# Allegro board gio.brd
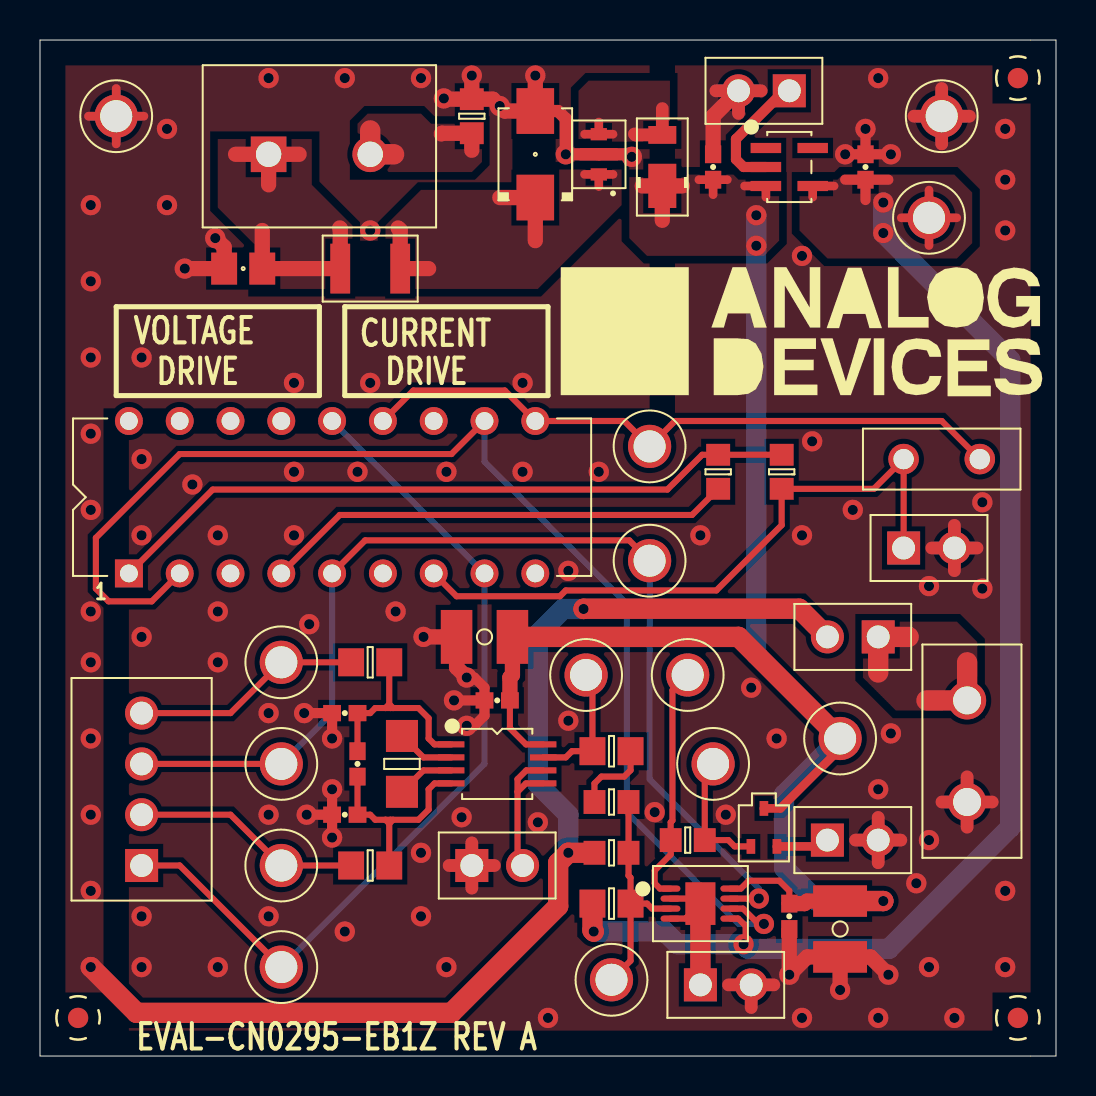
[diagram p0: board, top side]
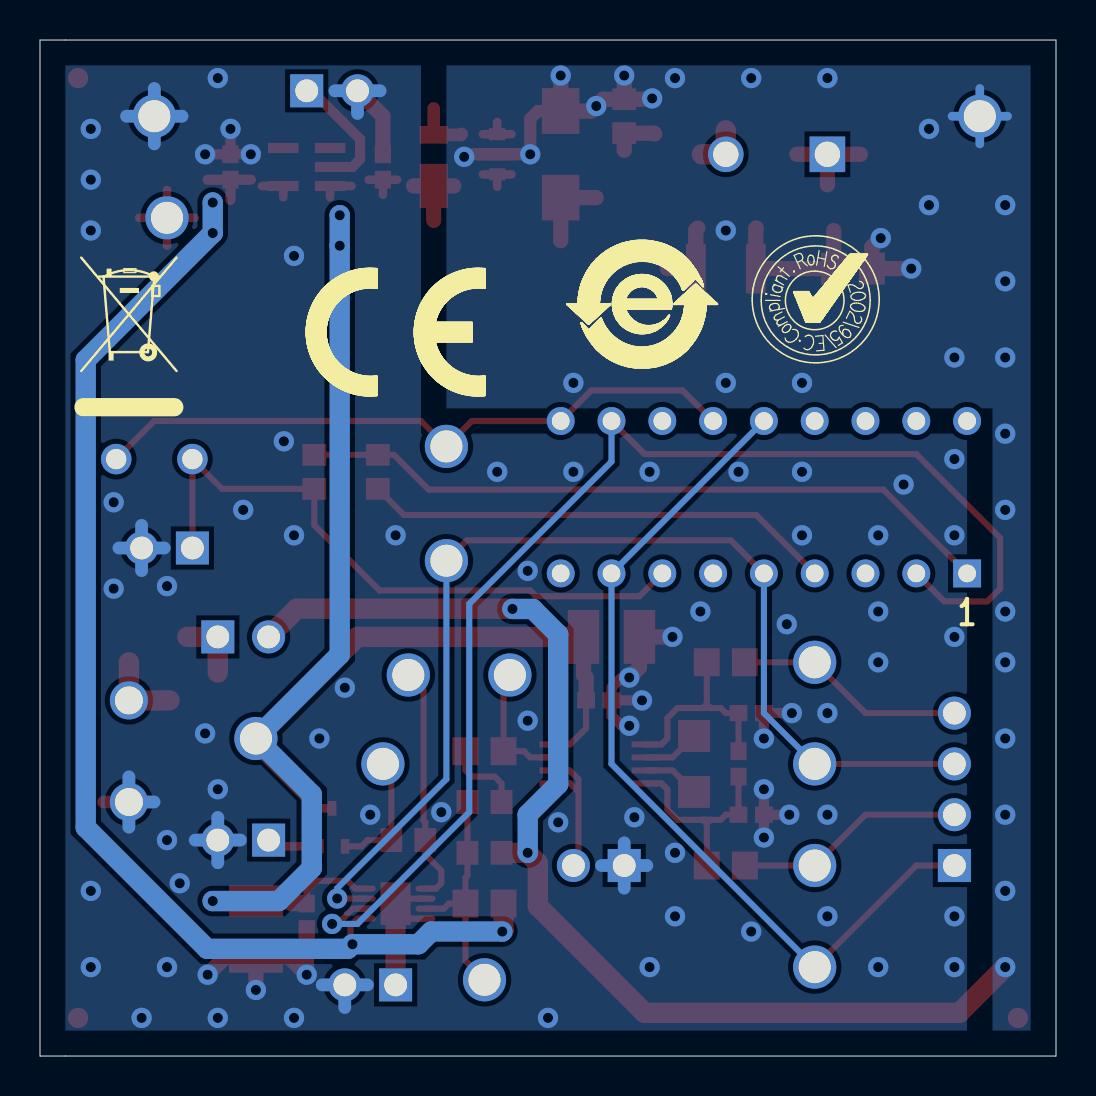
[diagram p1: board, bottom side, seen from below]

Outline 50.8 x 50.8 mm; copper layers: TOP, BOTTOM. Coordinates in mm from the lower left corner of the outline.
Outline path: 0,50.8 50.8,50.8 50.8,0 0,0 0,50.8

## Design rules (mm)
nets with their own width: min track width 0.508; nets AGND

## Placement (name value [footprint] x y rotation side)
C1  1000pF  [C0402]  15.24 17.14 180 top
C2  1000pF  [C0402]  15.24 12.06 0 top
C3  10000pF  [C0402]  15.88 14.6 270 top
C4  10uF  [C1210]  22.23 20.96 0 top
C5  1000pF  [C0402]  22.86 17.78 0 top
C6  10uF  [C1210]  40.01 6.35 90 top
C7  1000pF  [C0402]  37.47 6.99 90 top
C8  1000pF  [C0402]  33.66 44.45 270 top
C9  1000pF  [C0402]  41.27 44.45 270 top
C10  4.7UF  [C0805]  10.16 39.37 0 top
D1  SMAZ36-TP  [DIOSMJ5_0]  24.77 45.09 90 top
D2  SBR2U30P1-7  [POWERDI123]  31.12 44.45 90 top
F1  0.20A  [F1210]  16.51 39.37 0 top
FL1  0.1uF  [FSM0805L79W49H34]  27.94 45.09 90 top
GND  K24A W. EYELET T15.23  [CNLOOPTP]  45.09 46.99 0 top
GNDSNS  K24A W. EYELET T15.23  [CNLOOPTP]  12.06 4.45 0 top
J1  M20-9990246  [CNHARWIN-M20-9990246]  21.59 9.53 0 top
J2  OSTTC022162  [CN1X2H406]  11.43 45.09 0 top
J3  282834-4  [CN1X4H406]  5.08 9.53 90 top
J4  M20-9990246  [CNHARWIN-M20-9990246]  33.02 3.56 0 top
J5  M20-9990246  [CNHARWIN-M20-9990246]  37.47 48.26 180 top
J6  M20-9990246  [CNHARWIN-M20-9990246]  41.91 20.96 180 top
J7  M20-9990246  [CNHARWIN-M20-9990246]  43.18 25.4 0 top
J8  M20-9990246  [CNHARWIN-M20-9990246]  39.37 10.79 0 top
LOOPGND  K24A W. EYELET T15.23  [CNLOOPTP]  3.81 46.99 0 top
NOREF  -  []  0 0 0 top
NOREF#2  -  []  -132.72 -239.08 0 top
NOREF#3  -  [unnamed#2]  1.91 1.91 0 top
NOREF#4  -  []  76.2 0 90 top
NOREF#5  -  [unnamed#2]  48.9 48.9 0 top
NOREF#6  -  []  0 50.8 0 top
NOREF#7  -  []  -30.8 140.02 0 top
NOREF#8  -  []  1.91 1.91 0 top
NOREF#9  -  []  50.8 50.8 180 top
NOREF#10  -  []  38.73 36.2 0 top
NOREF#11  -  []  0 0 0 top
NOREF#12  -  []  24.64 73.91 0 top
NOREF#13  -  []  -132.72 -239.08 0 top
NOREF#14  -  []  -132.72 -239.08 0 top
NOREF#15  -  []  0 50.8 270 top
NOREF#16  -  []  0 0 0 top
NOREF#17  -  []  50.8 0 90 top
NOREF#18  -  []  0 50.8 0 top
NOREF#19  -  [unnamed#2]  48.9 1.91 0 top
NOREF#20  -  []  -15.88 -47.12 0 top
NOREF#21  -  []  1.91 1.91 0 top
NOREF#22  -  []  50.8 0 0 top
NOREF#23  -  []  31.5 36.2 180 bottom
NOREF#24  -  []  12.06 37.72 180 bottom
NOREF#25  -  []  46.36 37.08 180 bottom
NOREF#26  -  []  20.7 37.59 180 bottom
Q1  2SD2703TL  [TUMT3]  36.2 11.43 0 top
R1  4.02K  [R0805]  16.51 19.69 0 top
R2  4.02K  [R0805]  16.51 9.53 0 top
R3  1K  [R1206]  18.1 14.6 90 top
R4  2.5K  [RCK02]  43.18 29.85 0 top
R5  10K  [R0603]  33.91 29.21 90 top
R6  10K  [R0603]  37.08 29.21 90 top
R7  249  [R0603]  21.59 46.99 90 top
R8  2.0K  [R0805]  28.58 15.24 0 top
R9  30K  [R0603]  28.58 12.7 0 top
R10  1K  [R0603]  28.58 10.16 0 top
R11  30K  [R0603]  32.38 10.79 0 top
R12  130K  [R0805]  28.58 7.62 180 top
R13  10  [TO220AC-RA]  46.36 17.78 270 top
S1  ASE6204  [SWDIP18]  4.45 24.13 0 top
SUPPLYSNS  K24A W. EYELET T15.23  [CNLOOPTP]  12.06 14.6 0 top
TP1  K24A W. EYELET T15.23  [CNLOOPTP]  32.38 19.05 0 top
TP2  K24A W. EYELET T15.23  [CNLOOPTP]  44.45 41.91 0 top
TP3  K24A W. EYELET T15.23  [CNLOOPTP]  33.66 14.6 0 top
TP4  K24A W. EYELET T15.23  [CNLOOPTP]  27.3 19.05 0 top
TP5  K24A W. EYELET T15.23  [CNLOOPTP]  28.58 3.81 0 top
TP6  K24A W. EYELET T15.23  [CNLOOPTP]  30.48 24.77 0 top
TP7  K24A W. EYELET T15.23  [CNLOOPTP]  30.48 30.48 0 top
TP8  K24A W. EYELET T15.23  [CNLOOPTP]  40.01 15.88 0 top
U1  AD8226BRMZ  [MSOP8]  22.86 14.6 270 top
U2  ADA4091-2ACPZ  [QFN8_3X3_PAD2_13X1_5]  33.02 7.62 270 top
U3  ADR02BUJZ  [TSOT-5]  37.47 44.45 270 top
UNK+V  K24A W. EYELET T15.23  [CNLOOPTP]  12.06 9.53 0 top
UNK-V  K24A W. EYELET T15.23  [CNLOOPTP]  12.06 19.69 0 top

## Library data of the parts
C1 C2 C5 C7-C9 = CAP: Tolerance: 5; User Part Number: UPN; alternate symbols: (C0402H22_ALT,C0201-2); part number: CAP_SM-1000PF,50V,5,E012419,C0402; tolerance: 5
C3 = CAP: Tolerance: 10; User Part Number: UPN; alternate symbols: (C0402H22_ALT,C0201-2); part number: CAP_SM-10000PF,25V,10,E013688,C0402; tolerance: 10
C4 C6 = CAP: Tolerance: 10; User Part Number: UPN; alternate symbols: (C0402H22_ALT,C0201-2); part number: CAP_SM-10UF,25V,10,E011786,C1210; tolerance: 10
C10 = CAP: Tolerance: 10; User Part Number: UPN; alternate symbols: (C0402H22_ALT,C0201-2); part number: CAP_SM-4.7UF,25V,10,E006908,C0805; tolerance: 10
D1 = DIOZNR: Tolerance: 5; User Part Number: UPN; part number: DIOZNR_SM-SMAZ36-TP,36V,5,E017811,DIOSMJ5_0; tolerance: 5
D2 = DIO: User Part Number: UPN; Tolerance: N/A; part number: DIO_SM-SBR2U30P1-7,30V,N/A,E016912,POWERDI123; tolerance: N/A
F1 = FSFUSE: User Part Number: UPN; part number: FSFUSE_SM-0.20A,30V,E016947,F1210
FL1 = FLTR3P: Tolerance: 20; User Part Number: UPN; part number: FLTR3P_SM-0.1UF,E010964,FSM0805L79W49H34; tolerance: 20
GND GNDSNS LOOPGND SUPPLYSNS TP1-TP8 UNK+V UNK-V = CNTP1P: User Part Number: UPN; part number: CNTP1P_TH-K24A W. EYELET T15.23,E005673,CNLOOPTP
J1 J4-J8 = CN2P: User Part Number: UPN; part number: CN2P_TH-M20-9990246,E010843,CNHARWIN-M20-9990246
J2 = CN2P: User Part Number: UPN; part number: CN2P_TH-OSTTC022162,E016936,CN1X2H406
J3 = CN4P: User Part Number: UPN; part number: CN4P_TH-282834-4,E016935,CN1X4H406
Q1 = TRAN2N3904SOT23: User Part Number: UPN; part number: TRAN2N3904SOT23_SM-2SD2703TL,E016915,TUMT3
R1 R2 = RES: Tolerance: 1; User Part Number: UPN; alternate symbols: (RRAD984L1500W75H520LD32); part number: RES_SM-4.02K,1/8W,1,E003522,R0805; tolerance: 1
R3 = RES: Tolerance: 0.05; User Part Number: UPN; alternate symbols: (RRAD984L1500W75H520LD32); part number: RES_SM-1K,1/4W,0.05,E004440,R1206; tolerance: 0.05
R4 = RES: Tolerance: 0.005; User Part Number: UPN; alternate symbols: (RRAD984L1500W75H520LD32); part number: RES_TH-2.5K,0.6W,0.005,E017769,RCK02; tolerance: 0.005
R5 R6 = RES: Tolerance: 1; User Part Number: UPN; alternate symbols: (RRAD984L1500W75H520LD32); part number: RES_SM-10K,1/10W,1,E003671,R0603; tolerance: 1
R7 = RES: Tolerance: 0.1; User Part Number: UPN; alternate symbols: (RRAD984L1500W75H520LD32); part number: RES_SM-249,1/10W,0.1,E016628,R0603; tolerance: 0.1
R8 = RES: Tolerance: 0.1; User Part Number: UPN; alternate symbols: (RRAD984L1500W75H520LD32); part number: RES_SM-2.0K,1/10W,0.1,E003813,R0805; tolerance: 0.1
R9 R11 = RES: Tolerance: 0.1; User Part Number: UPN; alternate symbols: (RRAD984L1500W75H520LD32); part number: RES_SM-30K,1/10W,0.1,E003958,R0603; tolerance: 0.1
R10 = RES: Tolerance: 1; User Part Number: UPN; alternate symbols: (RRAD984L1500W75H520LD32); part number: RES_SM-1K,1/10W,1,E003678,R0603; tolerance: 1
R12 = RES: Tolerance: 1; User Part Number: UPN; alternate symbols: (RRAD984L1500W75H520LD32); part number: RES_SM-130K,1/8W,1,E003566,R0805; tolerance: 1
R13 = RES_INT: User Part Number: UPN; Tolerance: 0.5; alternate symbols: (TO220H590_ALT); part number: RES_INT_TH-10,2.25W,0.5,E003173,TO220AC-RA; tolerance: 0.5
S1 = SW6PDT: User Part Number: UPN; part number: SW6PDT_TH-ASE6204,E016934,SWDIP18
U1 = AD8220: User Part Number: UPN; part number: AD8220_SM-AD8226BRMZ,E013818,MSOP8,N/A
U2 = ADA4091_2: User Part Number: UPN; part number: ADA4091_2_SM-ADA4091-2ACPZ,E016852,QFN8_3X3_PAD2_13X1_5,N/A
U3 = ADR0X: User Part Number: UPN; part number: ADR0X_SM-ADR02BUJZ,E016933,TSOT-5,N/A

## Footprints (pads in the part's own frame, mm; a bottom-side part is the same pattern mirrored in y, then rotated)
C0402
  rect 0.889x0.813 smd: 1(-0.635,0) 2(0.635,0)
C0805
  rect 1.295x1.6 smd: 1(-0.953,0) 2(0.953,0)
C1210
  rect 1.575x2.692 smd: 1(-1.397,0) 2(1.397,0)
CN1X2H406
  rect 1.778x1.778 hole 1.27: 1(0,0)
  round 1.778 hole 1.27: 2(5.08,0)
CN1X4H406
  rect 1.651x1.651 hole 1.143: 1(0,0)
  round 1.651 hole 1.143: 2(2.54,0) 3(5.08,0) 4(7.62,0)
CNHARWIN-M20-9990246
  rect 1.651x1.651 hole 1.143: 1(0,0)
  round 1.651 hole 1.143: 2(2.54,0)
CNLOOPTP
  round 2.159 hole 1.6: 1(0,0)
DIOSMJ5_0
  rect 2.286x1.88 smd: A(2.164,0) C(-2.164,0)
F1210
  rect 0.991x2.489 smd: 1(-1.499,0) 2(1.499,0)
FSM0805L79W49H34
  rect 0.61x0.813 smd: 1(-1.005,0) 3(1.005,0)
  rect 0.61x1.905 smd: 2(0,0)
MSOP8
  rect 0.305x1.321 smd: 1(-0.975,-2.3) 2(-0.325,-2.3) 3(0.325,-2.3) 4(0.975,-2.3) 5(0.975,2.3) 6(0.325,2.3) 7(-0.325,2.3) 8(-0.975,2.3)
POWERDI123
  rect 0.889x1.397 smd: A(1.606,0)
  rect 2.21x1.397 smd: C(-0.945,0)
QFN8_3X3_PAD2_13X1_5
  oval 0.305x0.991 smd: 1(-0.75,-1.495) 2(-0.25,-1.495) 3(0.25,-1.495) 4(0.75,-1.495) 5(0.75,1.495) 6(0.25,1.495) 7(-0.25,1.495) 8(-0.75,1.495)
  rect 2.134x1.499 smd: PAD(0,0)
R0603
  rect 1.092x1.194 smd: 1(-0.851,0) 2(0.851,0)
R0805
  rect 1.295x1.397 smd: 1(-0.953,0) 2(0.953,0)
R1206
  rect 1.6x1.6 smd: 1(-1.397,0) 2(1.397,0)
RCK02
  round 1.524 hole 1.016: 1(0,0) 2(3.81,0)
SWDIP18
  rect 1.397x1.397 hole 0.889: 1(0,0)
  round 1.397 hole 0.889: 2(2.54,0) 3(5.08,0) 4(7.62,0) 5(10.16,0) 6(12.7,0) 7(15.24,0) 8(17.78,0) 9(20.32,0) 10(20.32,7.62) 11(17.78,7.62) 12(15.24,7.62) 13(12.7,7.62) 14(10.16,7.62) 15(7.62,7.62) 16(5.08,7.62) 17(2.54,7.62) 18(0,7.62)
TO220AC-RA
  round 1.905 hole 1.397: 1(0,0) 2(5.08,0)
TSOT-5
  rect 0.508x1.524 smd: 1(-0.95,-1.17) 2(0,-1.17) 3(0.95,-1.17) 4(0.95,1.17) 5(-0.95,1.17)
TUMT3
  rect 0.432x0.737 smd: 1(-0.65,-0.95) 2(0.65,-0.95) 3(0,0.95)
unnamed#2
  round 1.016 smd: (0,0)

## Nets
+5V: C9.2(N2) R12.2(N2) TP2.1(N1) U2.5(+IN) U3.4(VOUT)
+VCC: C4.2(N2) C5.2(N2) C6.2(N2) C7.2(N2) C8.2(N2) D2.C(N) Q1.3(C) TP8.1(N1) U1.8(VS+) U2.8(+V) U3.3(VIN)
AGND: C1.2(N2) C2.1(N1) C4.1(N1) C5.1(N1) C6.1(N1) C7.1(N1) C8.1(N1) C9.1(N1) GND.1(N1) J1.1(N1) J4.2(N2) J5.2(N2) J7.2(N2) J8.2(N2) R13.2(N2)
DGND: C10.1(N1) D1.A(P) FL1.2(GND) J6.2(N2) LOOPGND.1(N1) R7.2(N2) R10.1(N1)
+V_SENSOR_OUTPUT: J3.2(N2) R2.1(N1) UNK+V.1
-V_SENSOR_OUTPUT: J3.4(N4) R1.1(N1) UNK-V.1
OUTA: R11.1(N1) TP1.1(N1) U2.1(OUT)
SENSOR_GND: GNDSNS.1(N1) J3.1(N1) S1.8(C3) S1.14(C5)
SENSOR_SUPPLY: J3.3(N3) S1.5(C2) SUPPLYSNS.1(N1) TP6.1(N1) U2.7(OUT)
UNNAMED_2_AD8220_I94_IN: C1.1(N1) C3.1(N1) R1.2(N2) U1.1(IN-)
UNNAMED_2_AD8220_I94_IN_1: C2.2(N2) C3.2(N2) R2.2(N2) U1.4(IN+)
UNNAMED_2_AD8220_I94_OUT: R8.1(N1) TP4.1(N1) U1.7(OUT)
UNNAMED_2_AD8220_I94_REF: J1.2(N2) U1.5(VS-) U1.6(REF)
UNNAMED_2_AD8220_I94_RG: R3.2(N2) U1.2(RG)
UNNAMED_2_AD8220_I94_RG1: R3.1(N1) U1.3(RG1)
UNNAMED_2_ADA40912_I91_: J4.1(N1) U2.2(-IN) U2.4(-V) U2.PAD(-V1)
UNNAMED_2_ADA40912_I91__1: R9.2(N2) R10.2(N2) R12.1(N1) TP5.1(N1) U2.3(+IN)
UNNAMED_2_ADA40912_I92_: S1.2(C1) S1.11(C4) U2.6(-IN)
UNNAMED_2_ADR0X_I182_GND: J5.1(N1) U3.2(GND)
UNNAMED_2_CAP_I98_N2: C10.2(N2) F1.1(N1) J2.1(N1)
UNNAMED_2_CN2P_I187_N2: J2.2(N2) R7.1(N1)
UNNAMED_2_CN2P_I189_N1: J7.1(N1) R4.1(N1) R6.1(N1) S1.7(NC3)
UNNAMED_2_CN2P_I191_N1: J8.1(N1) Q1.2(E)
UNNAMED_2_CN2P_I192_N1: J6.1(N1) R13.1(N1)
UNNAMED_2_CNTP1P_I136_N1: Q1.1(B) R11.2(N2) TP3.1(N1)
UNNAMED_2_CNTP1P_I152_N1: R4.2(N2) S1.10(NO4) S1.13(NO5) TP7.1(N1)
UNNAMED_2_DIO_I100_P: D2.A(P) FL1.3(OUT)
UNNAMED_2_FLTR3P_I123_IN: D1.C(N) F1.2(N2) FL1.1(IN)
UNNAMED_2_RES_I109_N1: R8.2(N2) R9.1(N1)
UNNAMED_2_RES_I113_N1: R5.1(N1) S1.4(NC2)
UNNAMED_2_RES_I113_N2: R5.2(N2) R6.2(N2) S1.1(NC1)

Pads without a net: S1 3 6 9 12 15 16 17 18; U3 1 5

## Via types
v1: diameter 1.016, hole 0.508, TOP to BOTTOM, 111 vias

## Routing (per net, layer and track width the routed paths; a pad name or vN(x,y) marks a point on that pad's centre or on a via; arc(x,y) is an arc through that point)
+5V: length 71.2
  TOP w0.305: v1(35.18,5.59) 35.28,5.69 35.28,6.5 34.91,6.87 U2.5
  TOP w0.432: TP2.1 44.45,43.29 ; TP2.1 43.07,41.91 ; TP2.1 45.83,41.91 ; TP2.1 44.45,40.53 ; 39.7,43.5 U3.4 38.63,42.94
  TOP w0.508: C9.2 42.42,43.81 ; C9.2 41.27,42.8 ; C9.2 40.26,43.81
  TOP w1.016: R12.2 27.62,6.29 v1(27.69,6.22)
  BOTTOM w1.016: v1(27.69,6.22) 31.24,6.22 31.88,5.59 v1(35.18,5.59) 35.41,5.36 42.44,5.36 48.51,11.43 48.51,34.8 v1(42.16,41.15) v1(42.16,42.67)
+VCC: length 88.1
  TOP w0.305: C7.2 37.47,8.25 36.96,8.76 35.43,8.76 35.04,8.37 U2.8 ; U1.8 24.3,15.58 23.5,16.38 C5.2
  TOP w0.432: 35.23,43.5 U3.3 36.3,42.94 ; C8.2 34.37,43.81 ; C8.2 32.94,43.81 ; C8.2 33.66,43.07 ; TP8.1 40.01,15.37 37.02,12.38 Q1.3
  TOP w0.762: C4.2 23.62,19.05 23.5,18.92 C5.2 ; D2.C 30.11,43.5 ; D2.C 32.12,43.5 ; D2.C 31.12,41.78 ; C6.2 38.35,7.75 38.23,7.62 C7.2
  TOP w1.016: TP8.1 34.93,20.96 C4.2 ; C6.2 v1(42.16,7.75)
  BOTTOM w1.016: v1(42.16,7.75) 38.86,7.75 37.21,9.4 37.21,13.08 TP8.1 35.81,20.07 v1(35.81,40.51) v1(35.81,42.04)
AGND: length 92.8
  TOP w0.508: C5.1 22.23,17.02 21.72,16.51 v1(21.34,16.51) ; C5.1 v1(20.7,17.78) ; C5.1 22.23,18.42 21.72,18.92 v1(21.34,18.92) ; C9.1 v1(40.26,45.09) ; C9.1 v1(42.55,45.09) ; C9.1 v1(41.27,46.36) ; C2.1 v1(14.6,13.33) ; C2.1 v1(14.6,10.92) ; C2.1 v1(13.33,12.06) ; v1(13.21,17.14) C1.2 v1(14.6,15.88)
  TOP w0.635: J8.2 43.04,10.79 ; J8.2 41.91,11.93 ; J8.2 40.78,10.79 ; J8.2 41.91,9.66 ; 43.7,46.99 GND.1 ; GND.1 46.47,46.99 ; GND.1 45.09,45.61 ; GND.1 45.09,48.37 ; J7.2 46.85,25.4 ; J7.2 45.72,26.53 ; J7.2 45.72,24.27 ; J7.2 44.59,25.4 ; R13.2 47.61,12.7 ; R13.2 45.1,12.7 ; R13.2 46.36,13.96 ; R13.2 46.36,11.44 ; 33.79,48.26 J5.2 ; J5.2 36.06,48.26 ; J5.2 34.93,47.13 ; 21.59,8.39 J1.1 ; J1.1 22.72,9.53 ; J1.1 21.59,10.66 ; J1.1 20.46,9.53 ; J4.2 36.69,3.56 ; J4.2 35.56,2.43 ; J4.2 34.43,3.56
  TOP w0.762: v1(19.18,20.96) C4.1 20.83,19.43 v1(21.34,18.92) ; C6.1 41.53,4.95 v1(42.42,4.06) ; C6.1 v1(40.01,3.3) ; C6.1 38.35,4.95 v1(37.47,4.06) C7.1 ; C8.1 33.66,46.99 J5.2
  BOTTOM w0.635: 44.59,25.4 J7.2 ; J7.2 46.85,25.4 ; J7.2 45.72,24.27 ; J7.2 45.72,26.53 ; 34.93,47.13 J5.2 ; J5.2 33.79,48.26 ; J5.2 36.06,48.26 ; 35.56,2.43 J4.2 ; J4.2 34.43,3.56 ; J4.2 36.69,3.56 ; 45.09,45.61 GND.1 ; GND.1 45.09,48.37 ; GND.1 43.7,46.99 ; GND.1 46.47,46.99 ; 46.36,11.44 R13.2 ; R13.2 45.1,12.7 ; R13.2 46.36,13.96 ; 20.46,9.53 J1.1 ; J1.1 21.59,10.66 ; J1.1 21.59,8.39 ; J1.1 22.72,9.53 ; J8.2 43.04,10.79 ; J8.2 40.78,10.79 ; J8.2 41.91,9.66 ; J8.2 41.91,11.93
  vias: v1(5.08,29.85) v1(5.08,26.04) v1(5.08,20.96) v1(5.08,6.99) v1(5.08,4.45) v1(7.62,28.58) v1(8.89,26.04) v1(8.89,22.23) v1(8.89,19.69) v1(8.89,4.45) v1(11.43,17.14) v1(11.43,12.06) v1(11.43,6.99) v1(12.7,29.21) v1(12.7,26.04) v1(13.46,21.59) v1(15.24,6.22) v1(15.88,29.21) v1(17.78,22.23) v1(19.05,10.16) v1(19.05,6.99) v1(20.32,29.21) v1(20.32,4.45) v1(21.08,11.94) v1(24.13,29.21) v1(24.89,11.68) v1(25.4,1.91) v1(26.42,24.26) v1(26.42,16.76) v1(27.94,29.21) v1(30.73,12.19) v1(33.02,26.04) v1(34.29,12.06) v1(35.56,18.42) v1(36.83,15.88) v1(38.1,40.01) v1(38.1,26.04) v1(38.1,1.91) v1(38.61,30.73) v1(40.64,27.3) v1(41.91,48.9) v1(41.91,13.33) v1(41.91,1.91) v1(42.55,16.13) v1(43.81,8.64) v1(44.45,23.5) v1(44.45,10.79) v1(44.45,4.45) v1(45.72,1.91) v1(47.12,27.69) v1(47.12,23.37) v1(48.26,46.36) v1(48.26,43.81) v1(48.26,41.27) v1(48.26,8.25) v1(48.26,4.45)
DGND: length 87.2
  TOP w0.432: 2.43,46.99 LOOPGND.1 ; LOOPGND.1 3.81,48.37 ; LOOPGND.1 3.81,45.61 ; LOOPGND.1 5.19,46.99
  TOP w0.61: v1(29.59,44.96) 29.46,45.09 FL1.2 v1(26.29,45.09) 26.29,46.86 25.9,47.25 D1.A
  TOP w0.762: v1(7.24,39.37) C10.1 9.21,40.45 v1(8.76,40.89) ; R7.2 v1(21.59,49.02) ; R7.2 22.64,47.84 v1(22.99,47.5) 23.24,47.25 D1.A v1(24.77,49.02) ; R7.2 20.23,47.84 v1(20.19,47.88)
  TOP w1.016: v1(2.54,4.45) 4.83,2.16 20.57,2.16 25.91,7.49 25.91,9.65 v1(26.42,10.16) R10.1 ; J6.2 37.96,22.36 27.19,22.36 v1(27.18,22.35)
  BOTTOM w0.432: LOOPGND.1 3.81,48.37 ; LOOPGND.1 3.81,45.61 ; LOOPGND.1 5.19,46.99 ; LOOPGND.1 2.43,46.99
  BOTTOM w1.016: v1(27.18,22.35) 26.16,22.35 24.89,21.08 24.89,13.59 26.42,12.06 v1(26.42,10.16)
  vias: v1(2.54,42.55) v1(2.54,38.73) v1(2.54,34.93) v1(2.54,31.12) v1(2.54,27.3) v1(2.54,22.23) v1(2.54,19.69) v1(2.54,15.88) v1(2.54,12.06) v1(2.54,8.25) v1(5.08,34.93) v1(6.35,46.36) v1(6.35,42.55) v1(11.43,48.9) v1(12.7,33.66) v1(15.24,48.9) v1(16.51,41.27) v1(16.51,33.66) v1(19.05,48.9) v1(24.13,33.66)
+V_SENSOR_OUTPUT: length 11.5
  TOP w0.305: J3.2 9.53,12.06 UNK+V.1 R2.1
-V_SENSOR_OUTPUT: length 11.5
  TOP w0.305: R1.1 UNK-V.1 9.53,17.14 J3.4
OUTA: length 12
  TOP w0.305: U2.1 31,8.37 30.73,8.64 30.73,9.27 31.53,10.07 R11.1 31.53,11.68 31.62,11.77 31.62,18.29 TP1.1
SENSOR_GND: length 43.8
  TOP w0.305: GNDSNS.1 6.99,9.53 J3.1
  BOTTOM w0.305: GNDSNS.1 22.23,14.6 S1.8 14.6,31.75
SENSOR_SUPPLY: length 55.1
  TOP w0.305: TP6.1 29.46,25.78 16.26,25.78 S1.5 ; v1(35.94,7.87) 35.94,7.87 U2.7 ; J3.3 SUPPLYSNS.1
  BOTTOM w0.305: TP6.1 30.48,13.84 35.94,8.38 v1(35.94,7.87) ; SUPPLYSNS.1 14.6,17.14 S1.5
UNNAMED_2_AD8220_I94_IN: length 10.9
  TOP w0.305: 17.27,17.4 16.76,17.4 16.51,17.14 C1.1 15.88,15.24 ; 17.27,17.4 17.53,17.4 ; 17.27,17.4 17.46,17.59 ; 17.53,17.4 17.46,17.46 17.46,17.59 ; 17.53,17.4 17.65,17.4 ; 17.46,17.59 17.65,17.4 ; 17.46,17.59 R1.2 ; 17.65,17.4 18.92,17.4 19.43,16.89 19.43,15.88 19.73,15.58 U1.1
UNNAMED_2_AD8220_I94_IN_1: length 10.9
  TOP w0.305: 17.27,11.81 17.53,11.81 ; 17.27,11.81 17.46,11.62 ; 17.27,11.81 16.76,11.81 16.51,12.06 C2.2 C3.2 ; 17.53,11.81 17.46,11.75 17.46,11.62 ; 17.53,11.81 17.65,11.81 ; 17.46,11.62 17.65,11.81 ; 17.46,11.62 R2.2 ; 17.65,11.81 18.92,11.81 19.43,12.32 19.43,13.33 19.73,13.63 U1.4
UNNAMED_2_AD8220_I94_OUT: length 6.5
  TOP w0.305: U1.7 26.29,14.93 26.6,15.24 R8.1 27.62,18.73 TP4.1
UNNAMED_2_AD8220_I94_REF: length 7.3
  TOP w0.305: U1.5 24.3,13.63 23.88,13.21 ; 23.88,13.21 23.88,9.78 J1.2 ; 23.88,13.21 23.88,13.84 24.31,14.28 U1.6
UNNAMED_2_AD8220_I94_RG: length 2.9
  TOP w0.305: U1.2 19.17,14.93 R3.2
UNNAMED_2_AD8220_I94_RG1: length 2.9
  TOP w0.305: 18.1,13.21 19.17,14.28 U1.3
UNNAMED_2_ADA40912_I91_: length 7.5
  TOP w0.305: U2.2 32.77,7.87 U2.PAD 32.27,6.87 U2.4
  TOP w1.016: U2.PAD J4.1
UNNAMED_2_ADA40912_I91__1: length 11.4
  TOP w0.305: TP5.1 29.53,4.76 R12.1 ; R12.1 30.35,7.62 30.6,7.37 U2.3 ; R12.1 29.53,8.92 29.43,9.02 R10.2 R9.2
UNNAMED_2_ADA40912_I92_: length 63.1
  TOP w0.305: S1.2 5.59,22.73 3.43,22.73 2.79,23.37 2.79,25.91 6.99,30.1 20.57,30.1 22.23,31.75 ; v1(36.2,6.6) 35.92,6.6 35.15,7.37 U2.6
  BOTTOM w0.305: 22.23,31.75 22.23,29.72 29.34,22.61 29.34,12.19 34.93,6.6 v1(36.2,6.6)
UNNAMED_2_ADR0X_I182_GND: length 6.3
  TOP w0.508: U3.2 35.18,44.45 34.8,44.83 34.8,45.85 37.21,48.26 J5.1
UNNAMED_2_CAP_I98_N2: length 12.5
  TOP w0.762: 12.95,45.09 J2.1 ; J2.1 9.78,45.09 ; J2.1 11.43,43.56 ; 14.99,41.4 15.01,41.38 F1.1 C10.2 11.11,41.27
UNNAMED_2_CN2P_I187_N2: length 4.8
  TOP w0.762: 20.07,46.1 20.1,46.14 R7.1 21.59,45.29
  TOP w1.016: 16.51,46.28 J2.2 17.7,45.09
UNNAMED_2_CN2P_I189_N1: length 32.3
  TOP w0.305: J7.1 R4.1 41.69,28.36 R6.1 37.08,26.54 33.82,23.28 26.29,23.28 26,22.99 20.83,22.99 S1.7
UNNAMED_2_CN2P_I191_N1: length 2.7
  TOP w0.432: Q1.2 39.06,10.48 J8.1
UNNAMED_2_CN2P_I192_N1: length 7.2
  TOP w1.016: 43.43,20.96 J6.1 41.91,19.18 ; 46.36,19.69 R13.1 44.32,17.78
UNNAMED_2_CNTP1P_I136_N1: length 6.4
  TOP w0.305: Q1.1 34.73,10.48 34.42,10.79 R11.2 33.24,14.19 TP3.1
UNNAMED_2_CNTP1P_I152_N1: length 32.9
  TOP w0.305: 17.14,31.75 18.67,33.27 23.24,33.27 24.77,31.75 29.21,31.75 TP7.1 31.75,31.75 45.09,31.75 R4.2
UNNAMED_2_DIO_I100_P: length 4.8
  TOP w0.432: FL1.3 28.65,46.09 ; FL1.3 27.94,46.7 ; FL1.3 27.23,46.09
  TOP w0.635: 29.72,46.1 29.76,46.06 D2.A 31.12,47.37
UNNAMED_2_FLTR3P_I123_IN: length 9.5
  TOP w0.432: FL1.1 28.65,44.08 ; FL1.1 27.94,43.47 ; FL1.1 27.23,44.08
  TOP w0.762: 24.77,40.77 D1.C 22.99,42.92 ; 19.43,39.37 F1.2 18.01,41.3 17.91,41.4
UNNAMED_2_RES_I109_N1: length 4
  TOP w0.305: R9.1 27.72,13.63 28.07,13.97 29.21,13.97 29.53,14.29 R8.2
UNNAMED_2_RES_I113_N1: length 23.6
  TOP w0.305: S1.4 14.99,27.05 32.6,27.05 R5.1
UNNAMED_2_RES_I113_N2: length 35.1
  TOP w0.305: S1.1 8.64,28.32 31.37,28.32 33.11,30.06 R5.2 R6.2

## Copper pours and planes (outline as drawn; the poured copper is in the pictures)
+5V on TOP: 37.97,43.81 39.88,43.81 40.13,44.07 45.72,44.07 46.61,43.18 46.61,40.64 45.85,39.88 39.37,39.88 37.97,41.27
+VCC on TOP: 32.26,43.94 32.38,44.07 34.67,44.07 34.93,43.81 36.96,43.81 36.96,40.77 36.2,40.01 30.35,40.01 29.46,40.89 29.46,43.94
AGND on TOP: 4.45,1.27 4.45,31.12 31.75,31.12 31.75,49.53 47.62,49.53 47.62,47.62 49.53,47.62 49.53,3.17 47.62,3.17 47.62,1.27 ; 3 cut-outs
AGND on BOTTOM: 4.45,1.27 4.45,31.12 31.75,31.12 31.75,49.53 49.53,49.53 49.53,1.27
DGND on TOP: 1.27,3.17 1.27,49.53 30.48,49.53 30.48,32.38 3.17,32.38 3.17,3.17 ; 3 cut-outs
DGND on BOTTOM: 1.27,3.17 1.27,49.53 30.48,49.53 30.48,32.38 3.17,32.38 3.17,1.27 1.27,1.27 1.27,3.17
UNNAMED_2_CAP_I98_N2 on TOP: 8.89,45.85 13.59,45.85 13.59,43.56 15.62,41.53 15.62,38.35 10.79,38.35 10.79,40.51 8.89,42.42
UNNAMED_2_CN2P_I187_N2 on TOP: 22.1,46.61 22.1,44.7 21.59,44.2 15.88,44.2 15.88,46.61 16.38,47.12 19.05,47.12 19.56,46.61
UNNAMED_2_CN2P_I192_N1 on TOP: 41.15,21.72 45.85,21.72 46.86,20.7 46.86,17.27 42.8,17.27 41.15,18.92
UNNAMED_2_DIO_I100_P on TOP: 26.92,45.85 27.94,45.85 28.07,45.72 31.37,45.72 31.5,45.85 31.5,48.77 27.43,48.77 26.92,48.26
UNNAMED_2_FLTR3P_I123_IN on TOP: 17.27,38.35 24.89,38.35 29.08,42.55 29.08,44.32 25.15,44.32 24.13,43.31 19.05,43.31 17.27,41.53

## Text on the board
Ref Des/Silkscreen Top: VOLTAGE | EVAL-CN0295-EB1Z REV A | DRIVE | CURRENT
DIMENSION: REF
PAGE_OUTLINE: N/A | 24JUL12 | 10JAN13 | AD8226/ADA4091 CUSTOMER | EVALUATION BOARD | 20-035415
User.5: ROHS COMPLIANCE NOTE:  (Required for Customer Boards) Add to top of MATERIALS | 100 MICRO INCHES NICKEL/ | 3-5 MICRO INCHES GOLD | HOMOGENOUS MATERIALS IN THIS BOARD SHALL BE COMPLIANT | THE EU RoHS DIRECTIVE 2002/95/EC
User.8: 08-      -01 | LAYER1 PRIMARY SIDE
User.9: 08-      -02 | LAYER2 SECONDARY SIDE
User.11: 08-      -07 | LAYER2_AGND
User.12: 08-      -08 | LAYER3_DGND
User.14: SECONDARY SIDE PASTEMASK | 08-      -12
User.27: 20-035415
User.33: FIGURE | SIZE | 20.0 | 35.0 | 40.0 | 45.0 | 50.0 | 55.0 | 63.0 | DRILL CHART: TOP to BOTTOM | ALL UNITS ARE IN MILS | TOLERANCE | +3.0/-3.0 | PLATED | QTY | 111 | 18 | 2 | 9 | 7 | 1 | 14
